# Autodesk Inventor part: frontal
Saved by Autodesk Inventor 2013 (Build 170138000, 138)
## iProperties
Created: 2013-03
Part Number: frontal
Material: Generic
Document SubType Name: Modeling
Designer: julian.chica
Density: 1 g/cm^3
Author: julian.chica
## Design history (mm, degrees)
derived "Parlante_INICIAL.ipt"
feature "frontal::Parlante_INICIAL.ipt" dims "d0" = 10
tag "TaggingFeature1"
body "Solid1"
